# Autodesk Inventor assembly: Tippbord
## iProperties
Shininess: 64.0
Angle Display Precision: 2
Document Length Units: 11269
Document Angle Units: 11279
Document Time Units: 11290
Document Mass Units: 11283
Document Length Units Precision: 3
Document Angle Units Precision: 2
Created: 2001-12
Part Number: Tippbord
Document SubType Name: Assembly
Designer: Tobben
Density: 0.0
Volumn: 0.0
Area: 0.0
PropertySet Name: Model Information
Control State: 0
Master: False
Checked Out: False
Author: Tobben
